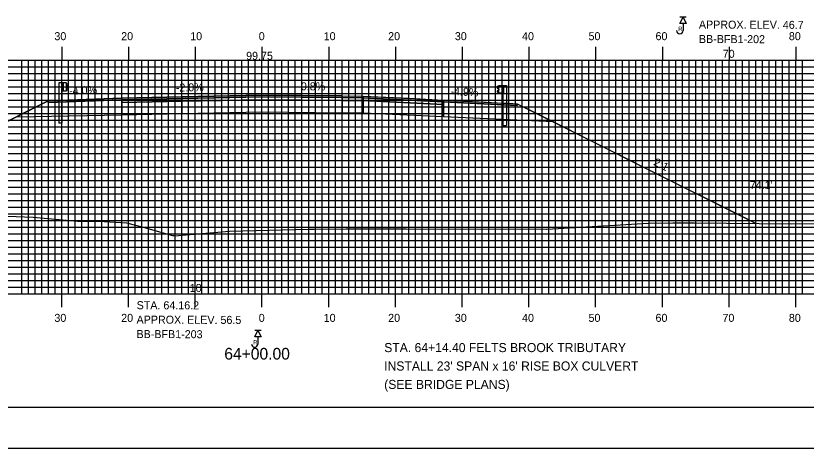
# Model space of a CAD drawing. Extents: x 1758643 to 1758986, y 442591 to 442811.
# Drawn here: x 1758771.8 to 1758890.2, y 442590.5 to 442655.3 of the extents above; entities that cross this region are included whole.
import ezdxf

# ---------------------------------------------------------------- set-up
doc = ezdxf.new("R2010")
doc.units = 0
for name, color, linetype in [('ANNOTATION', 7, 'Continuous'), ('BORDER', 7, 'Continuous'), ('BORING - REFUSAL', 7, 'Continuous'), ('D_Guardrail_Beam_Lt', 7, 'Continuous'), ('D_Guardrail_Beam_Rt', 7, 'Continuous'), ('D_Roadway_Centerline', 7, 'Continuous'), ('D_Roadway_Centerline_Text', 7, 'Continuous'), ('D_Roadway_Edge_Shoulder', 7, 'Continuous'), ('D_Roadway_Edge_TW', 7, 'Continuous'), ('D_Roadway_Pavement', 7, 'Continuous'), ('D_Roadway_SlopeLines', 7, 'Continuous'), ('D_Roadway_SubGrade', 7, 'Continuous'), ('D_Text_Standard', 7, 'Continuous'), ('H_V ANNOTATION', 7, 'Continuous'), ('MAJOR', 7, 'Continuous'), ('MINOR', 7, 'Continuous'), ('PLOT BOUNDARY', 7, 'Continuous'), ('S_Roadway_Centerline', 7, 'Continuous')]:
    doc.layers.add(name, color=color, linetype=linetype)

msp = doc.modelspace()

# ---------------------------------------------------------------- linework, layer by layer
at = {"layer": 'BORDER'}
msp.add_lwpolyline([(1758659.05, 442596.67), (1758979.05, 442596.67), (1758979.05, 442806.67), (1758659.05, 442806.67)], close=True, dxfattribs=at)
at = {"layer": 'BORING - REFUSAL'}
for p, q in [((1758872.23, 442655.12), (1758871.27, 442655.12)), ((1758871.75, 442654.16), (1758871.75, 442653.1)), ((1758808.53, 442608.17), (1758807.57, 442608.17)), ((1758808.05, 442607.21), (1758808.05, 442606.15))]:
    msp.add_line(p, q, dxfattribs=at)
for points in [[(1758871.75, 442655.12), (1758872.23, 442654.16), (1758871.27, 442654.16)], [(1758808.05, 442608.17), (1758808.53, 442607.21), (1758807.57, 442607.21)]]:
    msp.add_lwpolyline(points, close=True, dxfattribs=at)
for centre in [(1758871.26, 442653.1), (1758807.56, 442606.15)]:
    msp.add_arc(centre, 0.485, 180, 0, dxfattribs=at)
at = {"layer": 'D_Guardrail_Beam_Lt'}
for p, q in [((1758778.21, 442645.26), (1758778.21, 442639.26)), ((1758778.68, 442645.26), (1758778.21, 442645.26)), ((1758779.37, 442645.26), (1758778.68, 442645.26)), ((1758778.68, 442645.26), (1758778.68, 442644.09)), ((1758778.74, 442645.26), (1758778.74, 442644.09)), ((1758778.85, 442645.26), (1758778.85, 442644.09)), ((1758779.37, 442644.09), (1758779.37, 442645.26)), ((1758779.37, 442645.18), (1758779.44, 442645.16)), ((1758779.37, 442644.71), (1758779.37, 442644.64)), ((1758779.6, 442644.91), (1758779.41, 442644.77)), ((1758779.41, 442644.58), (1758779.6, 442644.44)), ((1758779.46, 442645.15), (1758779.6, 442645.05)), ((1758778.68, 442644.09), (1758779.37, 442644.09)), ((1758778.7, 442639.26), (1758778.7, 442644.09)), ((1758779.44, 442644.19), (1758779.37, 442644.18)), ((1758779.6, 442644.3), (1758779.46, 442644.2)), ((1758778.7, 442639.26), (1758778.21, 442639.26))]:
    msp.add_line(p, q, dxfattribs=at)
for centre, major_axis, start_param, end_param in [((1758779.45, 442644.71), (-0.0789, 0), 5.323254, 6.283185), ((1758779.45, 442644.64), (-0.0789, 0), 6.283185, 7.243116), ((1758779.44, 442645.12), (0.0417, 0), 0.959931, 1.376053), ((1758779.55, 442644.98), (0.0877, 0), 5.323254, 7.243116), ((1758779.55, 442644.37), (0.0877, 0), 5.323254, 7.243116), ((1758779.44, 442644.23), (0.0417, 0), 4.907132, 5.323254)]:
    msp.add_ellipse(centre, major_axis=major_axis, ratio=0.995501, start_param=start_param, end_param=end_param, dxfattribs=at)
at = {"layer": 'D_Guardrail_Beam_Rt'}
for p, q in [((1758844.05, 442644.78), (1758843.91, 442644.68)), ((1758843.91, 442644.54), (1758844.1, 442644.4)), ((1758844.14, 442644.8), (1758844.07, 442644.79)), ((1758844.14, 442644.89), (1758844.83, 442644.89)), ((1758844.14, 442643.72), (1758844.14, 442644.89)), ((1758844.66, 442644.89), (1758844.66, 442643.72)), ((1758844.76, 442644.89), (1758844.76, 442643.72)), ((1758844.83, 442644.89), (1758845.3, 442644.89)), ((1758844.83, 442644.89), (1758844.83, 442643.72)), ((1758845.3, 442644.89), (1758845.3, 442638.89)), ((1758844.1, 442644.2), (1758843.91, 442644.07)), ((1758843.91, 442643.92), (1758844.05, 442643.82)), ((1758844.07, 442643.82), (1758844.14, 442643.8)), ((1758844.13, 442644.34), (1758844.13, 442644.27)), ((1758844.83, 442643.72), (1758844.14, 442643.72)), ((1758844.81, 442638.89), (1758844.81, 442643.72)), ((1758844.81, 442638.89), (1758845.3, 442638.89))]:
    msp.add_line(p, q, dxfattribs=at)
for centre, major_axis, start_param, end_param in [((1758843.96, 442644.61), (-0.0877, 0), 5.323254, 7.243116), ((1758844.07, 442644.75), (-0.0417, 0), 4.907132, 5.323254), ((1758844.06, 442644.34), (0.0789, 0), 0, 0.959931), ((1758843.96, 442644), (-0.0877, 0), 5.323254, 7.243116), ((1758844.07, 442643.86), (-0.0417, 0), 0.959931, 1.376053), ((1758844.06, 442644.27), (0.0789, 0), 5.323254, 6.283185)]:
    msp.add_ellipse(centre, major_axis=major_axis, ratio=0.995501, start_param=start_param, end_param=end_param, dxfattribs=at)
at = {"layer": 'D_Roadway_Centerline'}
msp.add_lwpolyline([(1758739.49, 442623.98), (1758771.89, 442640.18), (1758776.64, 442642.56), (1758779.64, 442642.68), (1758787.64, 442643), (1758796.65, 442643.18), (1758808.65, 442643.42), (1758820.65, 442643.31), (1758823.83, 442643.29), (1758830.59, 442642.96), (1758835.85, 442642.7), (1758839.13, 442642.54), (1758842.23, 442642.38), (1758843.87, 442642.3), (1758845.59, 442642.22), (1758846.87, 442642.15), (1758848.82, 442641.18), (1758852.31, 442639.43), (1758854.14, 442638.52), (1758855.8, 442637.68), (1758868.84, 442631.16), (1758878.74, 442626.2), (1758880.26, 442625.44), (1758882.72, 442624.21)], dxfattribs=at)
at = {"layer": 'D_Roadway_Edge_Shoulder'}
for points in [[(1758787.64, 442643), (1758779.64, 442642.68), (1758779.64, 442642.68), (1758776.64, 442642.56), (1758776.64, 442642.31), (1758787.64, 442642.75)], [(1758835.85, 442642.7), (1758843.87, 442642.3), (1758843.87, 442642.3), (1758846.87, 442642.15), (1758846.87, 442641.9), (1758835.85, 442642.45)]]:
    msp.add_lwpolyline(points, close=True, dxfattribs=at)
at = {"layer": 'D_Roadway_Edge_TW'}
for points in [[(1758820.65, 442643.06), (1758820.65, 442643.31), (1758808.65, 442643.42), (1758796.65, 442643.18), (1758796.65, 442642.93), (1758808.65, 442643.17)], [(1758820.65, 442643.31), (1758823.83, 442643.29), (1758823.83, 442643.04), (1758820.65, 442643.06)], [(1758823.83, 442643.29), (1758835.85, 442642.7), (1758835.85, 442642.45), (1758823.83, 442643.04)], [(1758796.65, 442643.18), (1758787.64, 442643), (1758787.64, 442642.75), (1758796.65, 442642.93)]]:
    msp.add_lwpolyline(points, close=True, dxfattribs=at)
msp.add_lwpolyline([(1758820.65, 442643.31), (1758820.65, 442643.06)], dxfattribs=at)
msp.add_lwpolyline([(1758820.65, 442643.31), (1758820.65, 442643.06)], dxfattribs=at)
at = {"layer": 'D_Roadway_Pavement'}
for points in [[(1758796.65, 442642.93), (1758787.64, 442642.75), (1758787.64, 442642.33), (1758796.65, 442642.51)], [(1758820.65, 442642.65), (1758820.65, 442643.06), (1758808.65, 442643.17), (1758796.65, 442642.93), (1758796.65, 442642.51), (1758808.65, 442642.75)], [(1758820.65, 442643.06), (1758823.83, 442643.04), (1758823.83, 442642.62), (1758820.65, 442642.65)], [(1758823.83, 442643.04), (1758835.85, 442642.45), (1758835.85, 442642.03), (1758823.83, 442642.62)]]:
    msp.add_lwpolyline(points, close=True, dxfattribs=at)
for points in [[(1758787.64, 442642.75), (1758787.64, 442642.33)], [(1758787.64, 442642.75), (1758787.64, 442642.33)], [(1758820.65, 442643.06), (1758820.65, 442642.65)], [(1758820.65, 442643.06), (1758820.65, 442642.65)], [(1758835.85, 442642.45), (1758835.85, 442642.03)], [(1758835.85, 442642.45), (1758835.85, 442642.03)]]:
    msp.add_lwpolyline(points, dxfattribs=at)
at = {"layer": 'D_Roadway_SlopeLines'}
for points in [[(1758776.64, 442642.56), (1758739.49, 442623.98)], [(1758846.87, 442642.15), (1758882.72, 442624.21)]]:
    msp.add_lwpolyline(points, dxfattribs=at)
at = {"layer": 'D_Roadway_SubGrade'}
for points in [[(1758787.64, 442642.33), (1758787.64, 442642.75), (1758776.64, 442642.31), (1758776.64, 442642.56), (1758771.89, 442640.18), (1758787.64, 442640.5)], [(1758796.65, 442642.51), (1758787.64, 442642.33), (1758787.64, 442640.5), (1758796.65, 442640.68)], [(1758820.65, 442640.81), (1758820.65, 442642.65), (1758808.65, 442642.75), (1758796.65, 442642.51), (1758796.65, 442640.68), (1758808.65, 442640.92)], [(1758820.65, 442642.65), (1758823.83, 442642.62), (1758823.83, 442640.75), (1758820.65, 442640.81)], [(1758823.83, 442642.62), (1758835.85, 442642.03), (1758835.85, 442640.2), (1758823.83, 442640.75)], [(1758835.85, 442642.03), (1758835.85, 442642.45), (1758846.87, 442641.9), (1758846.87, 442642.15), (1758852.31, 442639.43), (1758835.85, 442640.2)]]:
    msp.add_lwpolyline(points, close=True, dxfattribs=at)
msp.add_lwpolyline([(1758820.65, 442642.65), (1758820.65, 442640.81)], dxfattribs=at)
msp.add_lwpolyline([(1758820.65, 442642.65), (1758820.65, 442640.81)], dxfattribs=at)
at = {"layer": 'MAJOR'}
for p, q in [((1758778.65, 442650.67), (1758778.65, 442648.67)), ((1758788.65, 442650.67), (1758788.65, 442648.67)), ((1758798.65, 442650.67), (1758798.65, 442648.67)), ((1758808.65, 442650.67), (1758808.65, 442648.67)), ((1758818.65, 442650.67), (1758818.65, 442648.67)), ((1758828.65, 442650.67), (1758828.65, 442648.67)), ((1758838.65, 442650.67), (1758838.65, 442648.67)), ((1758848.65, 442650.67), (1758848.65, 442648.67)), ((1758858.65, 442650.67), (1758858.65, 442648.67)), ((1758868.65, 442650.67), (1758868.65, 442648.67)), ((1758878.65, 442650.67), (1758878.65, 442648.67)), ((1758888.65, 442650.67), (1758888.65, 442648.67)), ((1758668.65, 442648.67), (1758948.65, 442648.67)), ((1758668.65, 442648.67), (1758948.65, 442648.67)), ((1758778.65, 442613.67), (1758778.65, 442648.67)), ((1758788.65, 442613.67), (1758788.65, 442648.67)), ((1758798.65, 442613.67), (1758798.65, 442648.67)), ((1758808.65, 442613.67), (1758808.65, 442648.67)), ((1758818.65, 442613.67), (1758818.65, 442648.67)), ((1758828.65, 442613.67), (1758828.65, 442648.67)), ((1758838.65, 442613.67), (1758838.65, 442648.67)), ((1758848.65, 442613.67), (1758848.65, 442648.67)), ((1758858.65, 442613.67), (1758858.65, 442648.67)), ((1758868.65, 442613.67), (1758868.65, 442648.67)), ((1758878.65, 442613.67), (1758878.65, 442648.67)), ((1758888.65, 442613.67), (1758888.65, 442648.67)), ((1758668.65, 442643.67), (1758948.65, 442643.67)), ((1758668.65, 442638.67), (1758948.65, 442638.67)), ((1758668.65, 442633.67), (1758948.65, 442633.67)), ((1758668.65, 442628.67), (1758948.65, 442628.67)), ((1758668.65, 442623.67), (1758948.65, 442623.67)), ((1758668.65, 442618.67), (1758948.65, 442618.67)), ((1758668.65, 442613.67), (1758948.65, 442613.67)), ((1758668.65, 442613.67), (1758948.65, 442613.67)), ((1758778.65, 442611.66), (1758778.65, 442613.67)), ((1758788.65, 442611.66), (1758788.65, 442613.67)), ((1758798.65, 442611.66), (1758798.65, 442613.67)), ((1758808.65, 442611.66), (1758808.65, 442613.67)), ((1758818.65, 442611.66), (1758818.65, 442613.67)), ((1758828.65, 442611.66), (1758828.65, 442613.67)), ((1758838.65, 442611.66), (1758838.65, 442613.67)), ((1758848.65, 442611.66), (1758848.65, 442613.67)), ((1758858.65, 442611.66), (1758858.65, 442613.67)), ((1758868.65, 442611.66), (1758868.65, 442613.67)), ((1758878.65, 442611.66), (1758878.65, 442613.67)), ((1758888.65, 442611.66), (1758888.65, 442613.67))]:
    msp.add_line(p, q, dxfattribs=at)
at = {"layer": 'MINOR'}
for p, q in [((1758772.65, 442613.67), (1758772.65, 442648.67)), ((1758773.65, 442613.67), (1758773.65, 442648.67)), ((1758774.65, 442613.67), (1758774.65, 442648.67)), ((1758775.65, 442613.67), (1758775.65, 442648.67)), ((1758776.65, 442613.67), (1758776.65, 442648.67)), ((1758777.65, 442613.67), (1758777.65, 442648.67)), ((1758779.65, 442613.67), (1758779.65, 442648.67)), ((1758780.65, 442613.67), (1758780.65, 442648.67)), ((1758781.65, 442613.67), (1758781.65, 442648.67)), ((1758782.65, 442613.67), (1758782.65, 442648.67)), ((1758783.65, 442613.67), (1758783.65, 442648.67)), ((1758784.65, 442613.67), (1758784.65, 442648.67)), ((1758785.65, 442613.67), (1758785.65, 442648.67)), ((1758786.65, 442613.67), (1758786.65, 442648.67)), ((1758787.65, 442613.67), (1758787.65, 442648.67)), ((1758789.65, 442613.67), (1758789.65, 442648.67)), ((1758790.65, 442613.67), (1758790.65, 442648.67)), ((1758791.65, 442613.67), (1758791.65, 442648.67)), ((1758792.65, 442613.67), (1758792.65, 442648.67)), ((1758793.65, 442613.67), (1758793.65, 442648.67)), ((1758794.65, 442613.67), (1758794.65, 442648.67)), ((1758795.65, 442613.67), (1758795.65, 442648.67)), ((1758796.65, 442613.67), (1758796.65, 442648.67)), ((1758797.65, 442613.67), (1758797.65, 442648.67)), ((1758799.65, 442613.67), (1758799.65, 442648.67)), ((1758800.65, 442613.67), (1758800.65, 442648.67)), ((1758801.65, 442613.67), (1758801.65, 442648.67)), ((1758802.65, 442613.67), (1758802.65, 442648.67)), ((1758803.65, 442613.67), (1758803.65, 442648.67)), ((1758804.65, 442613.67), (1758804.65, 442648.67)), ((1758805.65, 442613.67), (1758805.65, 442648.67)), ((1758806.65, 442613.67), (1758806.65, 442648.67)), ((1758807.65, 442613.67), (1758807.65, 442648.67)), ((1758809.65, 442613.67), (1758809.65, 442648.67)), ((1758810.65, 442613.67), (1758810.65, 442648.67)), ((1758811.65, 442613.67), (1758811.65, 442648.67)), ((1758812.65, 442613.67), (1758812.65, 442648.67)), ((1758813.65, 442613.67), (1758813.65, 442648.67)), ((1758814.65, 442613.67), (1758814.65, 442648.67)), ((1758815.65, 442613.67), (1758815.65, 442648.67)), ((1758816.65, 442613.67), (1758816.65, 442648.67)), ((1758817.65, 442613.67), (1758817.65, 442648.67)), ((1758819.65, 442613.67), (1758819.65, 442648.67)), ((1758820.65, 442613.67), (1758820.65, 442648.67)), ((1758821.65, 442613.67), (1758821.65, 442648.67)), ((1758822.65, 442613.67), (1758822.65, 442648.67)), ((1758823.65, 442613.67), (1758823.65, 442648.67)), ((1758824.65, 442613.67), (1758824.65, 442648.67)), ((1758825.65, 442613.67), (1758825.65, 442648.67)), ((1758826.65, 442613.67), (1758826.65, 442648.67)), ((1758827.65, 442613.67), (1758827.65, 442648.67)), ((1758829.65, 442613.67), (1758829.65, 442648.67)), ((1758830.65, 442613.67), (1758830.65, 442648.67)), ((1758831.65, 442613.67), (1758831.65, 442648.67)), ((1758832.65, 442613.67), (1758832.65, 442648.67)), ((1758833.65, 442613.67), (1758833.65, 442648.67)), ((1758834.65, 442613.67), (1758834.65, 442648.67)), ((1758835.65, 442613.67), (1758835.65, 442648.67)), ((1758836.65, 442613.67), (1758836.65, 442648.67)), ((1758837.65, 442613.67), (1758837.65, 442648.67)), ((1758839.65, 442613.67), (1758839.65, 442648.67)), ((1758840.65, 442613.67), (1758840.65, 442648.67)), ((1758841.65, 442613.67), (1758841.65, 442648.67)), ((1758842.65, 442613.67), (1758842.65, 442648.67)), ((1758843.65, 442613.67), (1758843.65, 442648.67)), ((1758844.65, 442613.67), (1758844.65, 442648.67)), ((1758845.65, 442613.67), (1758845.65, 442648.67)), ((1758846.65, 442613.67), (1758846.65, 442648.67)), ((1758847.65, 442613.67), (1758847.65, 442648.67)), ((1758849.65, 442613.67), (1758849.65, 442648.67)), ((1758850.65, 442613.67), (1758850.65, 442648.67)), ((1758851.65, 442613.67), (1758851.65, 442648.67)), ((1758852.65, 442613.67), (1758852.65, 442648.67)), ((1758853.65, 442613.67), (1758853.65, 442648.67)), ((1758854.65, 442613.67), (1758854.65, 442648.67)), ((1758855.65, 442613.67), (1758855.65, 442648.67)), ((1758856.65, 442613.67), (1758856.65, 442648.67)), ((1758857.65, 442613.67), (1758857.65, 442648.67)), ((1758859.65, 442613.67), (1758859.65, 442648.67)), ((1758860.65, 442613.67), (1758860.65, 442648.67)), ((1758861.65, 442613.67), (1758861.65, 442648.67)), ((1758862.65, 442613.67), (1758862.65, 442648.67)), ((1758863.65, 442613.67), (1758863.65, 442648.67)), ((1758864.65, 442613.67), (1758864.65, 442648.67)), ((1758865.65, 442613.67), (1758865.65, 442648.67)), ((1758866.65, 442613.67), (1758866.65, 442648.67)), ((1758867.65, 442613.67), (1758867.65, 442648.67)), ((1758869.65, 442613.67), (1758869.65, 442648.67)), ((1758870.65, 442613.67), (1758870.65, 442648.67)), ((1758871.65, 442613.67), (1758871.65, 442648.67)), ((1758872.65, 442613.67), (1758872.65, 442648.67)), ((1758873.65, 442613.67), (1758873.65, 442648.67)), ((1758874.65, 442613.67), (1758874.65, 442648.67)), ((1758875.65, 442613.67), (1758875.65, 442648.67)), ((1758876.65, 442613.67), (1758876.65, 442648.67)), ((1758877.65, 442613.67), (1758877.65, 442648.67)), ((1758879.65, 442613.67), (1758879.65, 442648.67)), ((1758880.65, 442613.67), (1758880.65, 442648.67)), ((1758881.65, 442613.67), (1758881.65, 442648.67)), ((1758882.65, 442613.67), (1758882.65, 442648.67)), ((1758883.65, 442613.67), (1758883.65, 442648.67)), ((1758884.65, 442613.67), (1758884.65, 442648.67)), ((1758885.65, 442613.67), (1758885.65, 442648.67)), ((1758886.65, 442613.67), (1758886.65, 442648.67)), ((1758887.65, 442613.67), (1758887.65, 442648.67)), ((1758889.65, 442613.67), (1758889.65, 442648.67)), ((1758668.65, 442647.67), (1758948.65, 442647.67)), ((1758668.65, 442646.67), (1758948.65, 442646.67)), ((1758668.65, 442645.67), (1758948.65, 442645.67)), ((1758668.65, 442644.67), (1758948.65, 442644.67)), ((1758668.65, 442642.67), (1758948.65, 442642.67)), ((1758668.65, 442641.67), (1758948.65, 442641.67)), ((1758668.65, 442640.67), (1758948.65, 442640.67)), ((1758668.65, 442639.67), (1758948.65, 442639.67)), ((1758668.65, 442637.67), (1758948.65, 442637.67)), ((1758668.65, 442636.67), (1758948.65, 442636.67)), ((1758668.65, 442635.67), (1758948.65, 442635.67)), ((1758668.65, 442634.67), (1758948.65, 442634.67)), ((1758668.65, 442632.67), (1758948.65, 442632.67)), ((1758668.65, 442631.67), (1758948.65, 442631.67)), ((1758668.65, 442630.67), (1758948.65, 442630.67)), ((1758668.65, 442629.67), (1758948.65, 442629.67)), ((1758668.65, 442627.67), (1758948.65, 442627.67)), ((1758668.65, 442626.67), (1758948.65, 442626.67)), ((1758668.65, 442625.67), (1758948.65, 442625.67)), ((1758668.65, 442624.67), (1758948.65, 442624.67)), ((1758668.65, 442622.67), (1758948.65, 442622.67)), ((1758668.65, 442621.67), (1758948.65, 442621.67)), ((1758668.65, 442620.67), (1758948.65, 442620.67)), ((1758668.65, 442619.67), (1758948.65, 442619.67)), ((1758668.65, 442617.67), (1758948.65, 442617.67)), ((1758668.65, 442616.67), (1758948.65, 442616.67)), ((1758668.65, 442615.67), (1758948.65, 442615.67)), ((1758668.65, 442614.67), (1758948.65, 442614.67))]:
    msp.add_line(p, q, dxfattribs=at)
at = {"layer": 'PLOT BOUNDARY'}
msp.add_lwpolyline([(1758642.86, 442590.55), (1758982.86, 442590.55), (1758982.86, 442810.55), (1758642.86, 442810.55)], close=True, dxfattribs=at)
at = {"layer": 'S_Roadway_Centerline'}
msp.add_lwpolyline([(1758767.94, 442625.41), (1758774.37, 442625.17), (1758781.01, 442624.57), (1758784.99, 442624.5), (1758788.36, 442624.31), (1758790.86, 442623.68), (1758795.24, 442622.41), (1758795.42, 442622.39), (1758795.53, 442622.38), (1758803.79, 442623.06), (1758815.72, 442623.35), (1758816.48, 442623.36), (1758821.27, 442623.39), (1758829.48, 442623.41), (1758830.27, 442623.4), (1758851.27, 442623.38), (1758851.28, 442623.38), (1758851.32, 442623.38), (1758866.59, 442624.24), (1758870.2, 442624.29), (1758873.46, 442624.33), (1758887.99, 442624.14), (1758900.68, 442624.27)], dxfattribs=at)

# ---------------------------------------------------------------- texts
at = {"layer": 'ANNOTATION'}
for s, rotation, p in [('-4.0%', 2.2906, (1758779.77, 442643.48)), ('-2.0%', 1.1458, (1758795.75, 442643.96)), ('-0.8%', 359.5192, (1758813.94, 442644.17)), ('-4.9%', 357.1745, (1758836.87, 442643.45)), ('2:1', 333.4054, (1758867.21, 442633.01))]:
    msp.add_text(s, height=1.2, rotation=rotation, dxfattribs=at).set_placement(p)
for s, p in [('STA. 64+14.40 FELTS BROOK TRIBUTARY', (1758826.97, 442604.94)), ("INSTALL 23' SPAN x 16' RISE BOX CULVERT", (1758826.97, 442602.18)), ('(SEE BRIDGE PLANS)', (1758826.97, 442599.42))]:
    msp.add_text(s, height=1.36, dxfattribs=at).set_placement(p)
at = {"layer": 'BORING - REFUSAL'}
for s, p in [('APPROX. ELEV. 46.7', (1758874.12, 442653.41)), ('BB-BFB1-202', (1758874.12, 442651.25)), ('STA. 64.16.2', (1758789.87, 442611.37)), ('APPROX. ELEV. 56.5', (1758789.86, 442609.21)), ('BB-BFB1-203', (1758789.85, 442607.05))]:
    msp.add_text(s, height=1.2, rotation=359.8142, dxfattribs=at).set_placement(p)
for p in [(1758871.04, 442653.05), (1758807.34, 442606.09)]:
    msp.add_text('R', height=0.64, dxfattribs=at).set_placement(p)
at = {"layer": 'D_Roadway_Centerline'}
for s, p in [('C', (1758808.64, 442643.42)), ('L', (1758808.65, 442643.41))]:
    msp.add_text(s, height=0.0146, dxfattribs=at).set_placement(p)
at = {"layer": 'D_Roadway_Centerline_Text'}
msp.add_text('99.75', height=1.2, dxfattribs=at).set_placement((1758806.28, 442648.73))
at = {"layer": 'D_Text_Standard'}
msp.add_text("74.1'", height=1.2, dxfattribs=at).set_placement((1758881.74, 442629.37))
at = {"layer": 'H_V ANNOTATION'}
for s, height, p in [('30', 1.2, (1758777.55, 442651.67)), ('20', 1.2, (1758787.56, 442651.67)), ('10', 1.2, (1758797.9, 442651.67)), ('0', 1.2, (1758808.17, 442651.67)), ('10', 1.2, (1758817.9, 442651.67)), ('20', 1.2, (1758827.56, 442651.67)), ('30', 1.2, (1758837.55, 442651.67)), ('40', 1.2, (1758847.62, 442651.67)), ('50', 1.2, (1758857.58, 442651.67)), ('60', 1.2, (1758867.62, 442651.67)), ('80', 1.2, (1758887.6, 442651.67)), ('70', 1.2, (1758877.69, 442649.03)), ('10', 1.2, (1758797.83, 442613.95)), ('30', 1.2, (1758777.55, 442609.47)), ('20', 1.2, (1758787.56, 442609.47)), ('0', 1.2, (1758808.17, 442609.47)), ('10', 1.2, (1758817.9, 442609.47)), ('20', 1.2, (1758827.56, 442609.47)), ('30', 1.2, (1758837.55, 442609.47)), ('40', 1.2, (1758847.62, 442609.47)), ('50', 1.2, (1758857.58, 442609.47)), ('60', 1.2, (1758867.62, 442609.47)), ('70', 1.2, (1758877.65, 442609.47)), ('80', 1.2, (1758887.6, 442609.47)), ('64+00.00', 1.75, (1758803.01, 442603.82))]:
    msp.add_text(s, height=height, dxfattribs=at).set_placement(p)

doc.saveas('drawing.dxf')
